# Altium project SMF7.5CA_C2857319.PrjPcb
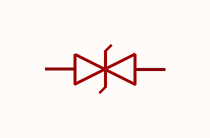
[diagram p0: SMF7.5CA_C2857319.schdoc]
1 sheet, 1 parts. Net scope: global (net labels, ports and power ports of the same name join across sheets).

## Sheet SMF7.5CA_C2857319.schdoc
size 127 x 101 mm

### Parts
D?  smf7.5ca_c2857319  [SOD-123FL_L2.8-W1.8-LS3.8-BI]  (value not drawn)

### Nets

Not connected (* = marked no-connect by the designer): D? 1 2

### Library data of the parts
D? = smf7.5ca_c2857319: 极性:双向;反向截止电压(Vrwm):7.5V;钳位电压:12.9V;峰值脉冲电流(Ipp):15.5A;峰值脉冲功率(Ppp):200W@10/1000us;击穿电压(VBR):8.33V;; Manufacturer: JSMSEMI(杰盛微); AddInBom: yes; ModelId: e6c5e89e00374f9c89f20ae06fb50805; ModelTransform: 147.6375,70.866,0,0,0,0,0,0,0; Polarity: 双向; Reverse Stand-Off Voltage (Vrwm): 7.5V; Clamping Voltage: 12.9V; Peak Pulse Current (Ipp): 15.5A; Voltage - Breakdown: 8.33V; Reverse Leakage Current (Ir): 50uA; Number of Channels: 单路; Type: TVS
